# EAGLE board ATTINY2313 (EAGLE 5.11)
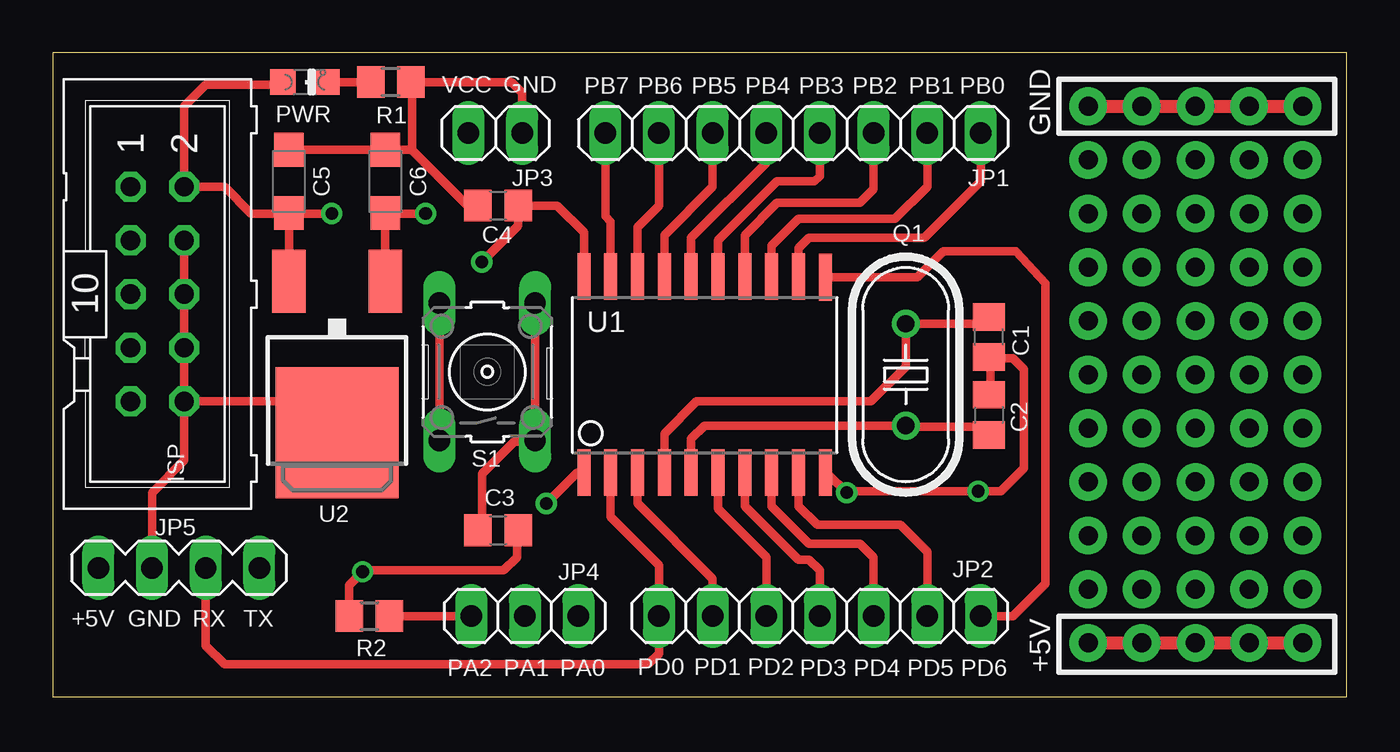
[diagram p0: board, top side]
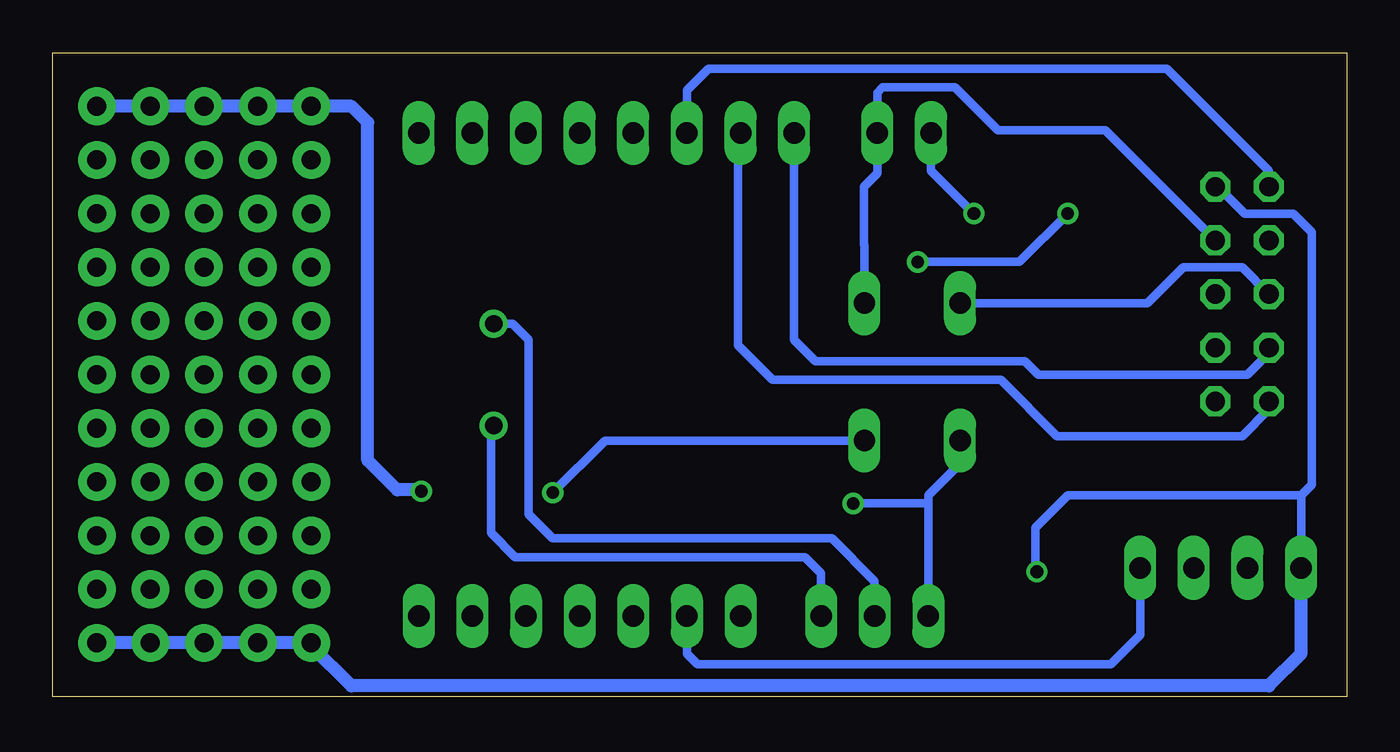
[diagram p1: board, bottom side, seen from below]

Size 61.27 x 30.47 mm. Coordinates in mm from the lower left corner, seen from the top.
Outline: 0,0 61.27,0 61.27,30.47 0,30.47 0,0
Copper layers (1*16): Top 0.035mm / dielectric 1.5mm / Bottom 0.035mm
Design rules "default": minimum track width 10mil, minimum drill 24mil, track to track 8mil, track to pad 8mil, pad to pad 8mil, via to via 8mil, smd to smd 8mil, copper to edge 40mil, drill to drill 8mil, minimum pad ring 10mil, minimum via ring 8mil, stop-mask expansion 4mil, vias tented up to drill 0mil, thermal gap 10mil

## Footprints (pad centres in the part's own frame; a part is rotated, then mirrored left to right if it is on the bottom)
C0805 = smd 1.3 x 1.5: 1 -0.95,0; 2 0.95,0
SMC_A = smd 1.6 x 1.4: + -1.5,0; - 1.5,0
ML10 = drill 0.914 octagon: 1 -5.08,-1.27; 2 -5.08,1.27; 3 -2.54,-1.27; 4 -2.54,1.27; 5 0,-1.27; 6 0,1.27; 7 2.54,-1.27; 8 2.54,1.27; 9 5.08,-1.27; 10 5.08,1.27
1X08 = drill 1.016 long: 1 -8.89,0; 2 -6.35,0; 3 -3.81,0; 4 -1.27,0; 5 1.27,0; 6 3.81,0; 7 6.35,0; 8 8.89,0
1X07 = drill 1.016 long: 1 -7.62,0; 2 -5.08,0; 3 -2.54,0; 4 0,0; 5 2.54,0; 6 5.08,0; 7 7.62,0
1X02 = drill 1.016 long: 1 -1.27,0; 2 1.27,0
1X03 = drill 1.016 long: 1 -2.54,0; 2 0,0; 3 2.54,0
MA04-1 = drill 1.016 long: 1 -3.81,0; 2 -1.27,0; 3 1.27,0; 4 3.81,0
CHIPLED_0805 = smd 1.2 x 1.2: A 0,-1.05; C 0,1.05
HC49U70 = drill 0.813 round: 1 -2.413,0; 2 2.413,0
R0805 = smd 1.3 x 1.5: 1 -0.95,0; 2 0.95,0
B3F-10XX = drill 1.016 long: 1 -3.251,2.261; 2 3.251,2.261; 3 -3.251,-2.261; 4 3.251,-2.261
SO20L$ = smd 0.61 x 2.21: 1 -5.715,-4.636; 2 -4.445,-4.636; 3 -3.175,-4.636; 4 -1.905,-4.636; 5 -0.635,-4.636; 6 0.635,-4.636; 7 1.905,-4.636; 8 3.175,-4.636; 9 4.445,-4.636; 10 5.715,-4.636; 11 5.715,4.61; 12 4.445,4.636; 13 3.175,4.636; 14 1.905,4.636; 15 0.635,4.636; 16 -0.635,4.636; 17 -1.905,4.636; 18 -3.175,4.636; 19 -4.445,4.636; 20 -5.715,4.636
DPACK = smd 1.6 x 3: 1 -2.28,-4.8; 3 2.28,-4.8 | smd 5.8 x 6.2: 4 0,2.38

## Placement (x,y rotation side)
C1  [C0805]  44.32,17.02 90 top
C2  [C0805]  44.32,13.33 270 top
C3  [C0805]  21.08,7.87 0 top
C4  [C0805]  21.08,23.24 0 top
C5  [SMC_A]  11.18,24.38 90 top
C6  [SMC_A]  15.75,24.38 90 top
ISP  [ML10]  4.95,19.05 270 top
JP1  [1X08]  35.05,26.67 0 top
JP2  [1X07]  36.32,3.81 180 top
JP3  [1X02]  20.95,26.67 0 top
JP4  [1X03]  22.35,3.81 180 top
JP5  AVTMOD09  [MA04-1]  5.97,6.1 0 top
PWR  [CHIPLED_0805]  11.94,29.08 270 top
Q1  [HC49U70]  40.39,15.24 90 top
R1  [R0805]  16,29.08 180 top
R2  [R0805]  14.99,3.81 0 top
S1  [B3F-10XX]  20.57,15.37 90 top
U1  TINY2313-*S*  [SO20L$]  30.86,15.24 0 top
U2  LP2950CDT-5.0  [DPACK]  13.46,14.86 180 top

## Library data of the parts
C1-C6 R1 R2 = rcl
ISP = con-ml
JP1-JP4 = pinhead
JP5 = con-lstb
PWR = led
Q1 = crystal
S1 = switch-omron
U1 = avr-6
U2 = v-reg

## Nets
GND: C1.1 C2.1 C3.1 C4.1 C5.- C6.- ISP.4 ISP.6 ISP.8 ISP.10 JP3.2 JP5.2 R1.1 S1.3 S1.4 U1.10 U2.4
N$6: PWR.C R1.2
PA0: C2.2 JP4.1 Q1.1 U1.5
PA1: C1.2 JP4.2 Q1.2 U1.4
PA2: ISP.5 JP4.3 R2.2 S1.1 S1.2 U1.1
PB0: JP1.8 U1.12
PB1: JP1.7 U1.13
PB2: JP1.6 U1.14
PB3: JP1.5 U1.15
PB4: JP1.4 U1.16
PB5: ISP.1 JP1.3 U1.17
PB6: ISP.9 JP1.2 U1.18
PB7: ISP.7 JP1.1 U1.19
PD0: JP2.7 JP5.3 U1.2
PD1: JP2.6 JP5.4 U1.3
PD2: JP2.5 U1.6
PD3: JP2.4 U1.7
PD4: JP2.3 U1.8
PD5: JP2.2 U1.9
PD6: JP2.1 U1.11
VCC: C3.2 C4.2 C5.+ ISP.2 JP5.1 PWR.A R2.1 U1.20 U2.3
VIN: C6.+ JP3.1 U2.1

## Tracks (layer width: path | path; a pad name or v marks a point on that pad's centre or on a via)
GND  (via drill 0.6, 0.9 pad 1.78)
  Top 0.406: 16.99,25.88 C6.- C5.- 16.99,25.88 | 17.02,25.91 17.02,29.02 R1.1 | C4.1 19.64,23.24 16.99,25.88 | ISP.4 ISP.6 ISP.8 ISP.10 | ISP.10 13.21,13.97 13.46,13.72 U2.4 | JP5.2 4.7,9.65 6.22,11.18 ISP.10 | S1.4 S1.3 22.78,12.06 21.84,12.06 20.32,10.54 20.32,8 20.19,7.87 C3.1 | 17.02,25.91 16.99,25.88 | 17.02,25.91 17.02,29.08 21.72,29.08 22.23,28.57 JP3.2 | v37.59,9.65 37.59,9.72 v43.81,9.72 | v43.81,9.72 44.9,9.72 45.97,10.79 45.97,15.49 45.47,16 44.39,16 | 44.39,16 C1.1 | 44.39,16 44.39,14.35 C2.1 | U1.10 36.64,10.6 v37.59,9.65 | v43.81,9.72 37.66,9.72 v37.59,9.65
  Top 0.61: v49.02,27.94 v59.18,27.94
  Bottom 0.406: ISP.4 11.43,26.8 16.51,26.8 18.54,28.83 21.97,28.83 22.23,28.57 JP3.2 22.23,24.76 22.86,24.13 22.86,21.39 22.84,21.36 S1.4 | S1.3 35.13,12.12 v37.59,9.65
  Bottom 0.61: 48.89,27.94 47.12,27.94 46.36,27.18 46.36,11.18 44.96,9.78 43.81,9.78 v43.81,9.72 | 48.89,27.94 v49.02,27.94 | 48.89,27.94 v59.18,27.94
N$2  (via drill 0.9 pad 1.78)
  other vias: 51.56,2.54
N$3  (via drill 0.9 pad 1.78)
  other vias: 54.1,2.54
N$4  (via drill 0.9 pad 1.78)
  other vias: 56.64,2.54
N$5  (via drill 0.9 pad 1.78)
  other vias: 59.18,2.54
N$6
  Top 0.406: PWR.C R1.2
N$12  (via drill 0.9 pad 1.78)
  other vias: 49.02,5.08
N$13  (via drill 0.9 pad 1.78)
  other vias: 51.56,5.08
N$14  (via drill 0.9 pad 1.78)
  other vias: 54.1,5.08
N$15  (via drill 0.9 pad 1.78)
  other vias: 56.64,5.08
N$16  (via drill 0.9 pad 1.78)
  other vias: 59.18,5.08
N$23  (via drill 0.9 pad 1.78)
  other vias: 49.02,7.62
N$24  (via drill 0.9 pad 1.78)
  other vias: 51.56,7.62
N$25  (via drill 0.9 pad 1.78)
  other vias: 54.1,7.62
N$26  (via drill 0.9 pad 1.78)
  other vias: 56.64,7.62
N$27  (via drill 0.9 pad 1.78)
  other vias: 59.18,7.62
N$34  (via drill 0.9 pad 1.78)
  other vias: 49.02,10.16
N$35  (via drill 0.9 pad 1.78)
  other vias: 51.56,10.16
N$36  (via drill 0.9 pad 1.78)
  other vias: 54.1,10.16
N$37  (via drill 0.9 pad 1.78)
  other vias: 56.64,10.16
N$38  (via drill 0.9 pad 1.78)
  other vias: 59.18,10.16
N$45  (via drill 0.9 pad 1.78)
  other vias: 49.02,12.7
N$46  (via drill 0.9 pad 1.78)
  other vias: 51.56,12.7
N$47  (via drill 0.9 pad 1.78)
  other vias: 54.1,12.7
N$48  (via drill 0.9 pad 1.78)
  other vias: 56.64,12.7
N$49  (via drill 0.9 pad 1.78)
  other vias: 59.18,12.7
N$56  (via drill 0.9 pad 1.78)
  other vias: 49.02,15.24
N$57  (via drill 0.9 pad 1.78)
  other vias: 51.56,15.24
N$58  (via drill 0.9 pad 1.78)
  other vias: 54.1,15.24
N$59  (via drill 0.9 pad 1.78)
  other vias: 56.64,15.24
N$60  (via drill 0.9 pad 1.78)
  other vias: 59.18,15.24
N$67  (via drill 0.9 pad 1.78)
  other vias: 49.02,17.78
N$68  (via drill 0.9 pad 1.78)
  other vias: 51.56,17.78
N$69  (via drill 0.9 pad 1.78)
  other vias: 54.1,17.78
N$70  (via drill 0.9 pad 1.78)
  other vias: 56.64,17.78
N$71  (via drill 0.9 pad 1.78)
  other vias: 59.18,17.78
N$78  (via drill 0.9 pad 1.78)
  other vias: 49.02,20.32
N$79  (via drill 0.9 pad 1.78)
  other vias: 51.56,20.32
N$80  (via drill 0.9 pad 1.78)
  other vias: 54.1,20.32
N$81  (via drill 0.9 pad 1.78)
  other vias: 56.64,20.32
N$82  (via drill 0.9 pad 1.78)
  other vias: 59.18,20.32
N$90  (via drill 0.9 pad 1.78)
  other vias: 49.02,22.86
N$91  (via drill 0.9 pad 1.78)
  other vias: 51.56,22.86
N$92  (via drill 0.9 pad 1.78)
  other vias: 54.1,22.86
N$93  (via drill 0.9 pad 1.78)
  other vias: 56.64,22.86
N$94  (via drill 0.9 pad 1.78)
  other vias: 59.18,22.86
N$95  (via drill 0.9 pad 1.78)
  other vias: 49.02,25.4
N$96  (via drill 0.9 pad 1.78)
  other vias: 51.56,25.4
N$97  (via drill 0.9 pad 1.78)
  other vias: 54.1,25.4
N$98  (via drill 0.9 pad 1.78)
  other vias: 56.64,25.4
N$99  (via drill 0.9 pad 1.78)
  other vias: 59.18,25.4
N$101  (via drill 0.9 pad 1.78)
  other vias: 51.56,27.94
N$102  (via drill 0.9 pad 1.78)
  other vias: 54.1,27.94
N$103  (via drill 0.9 pad 1.78)
  other vias: 56.64,27.94
PA0
  Top 0.406: U1.5 30.23,12.19 30.86,12.83 Q1.1 40.45,12.76 43.95,12.76 C2.2
  Bottom 0.406: JP4.1 24.89,5.84 25.65,6.6 39.37,6.6 40.51,7.75 40.51,12.7 Q1.1
PA1
  Top 0.406: U1.4 28.96,12.45 30.48,13.97 38.73,13.97 40.39,15.62 Q1.2 44.01,17.65 C1.2 44.13,17.65
  Bottom 0.406: JP4.2 22.35,5.46 24.38,7.49 37.59,7.49 38.73,8.64 38.73,16.89 39.5,17.65 Q1.2
PA2  (via drill 0.6)
  Top 0.406: R2.2 JP4.3 | S1.1 S1.2 | U1.1 24.83,10.6 v23.37,9.14
  Bottom 0.406: S1.1 18.31,11.02 19.81,9.52 19.81,9.14 | JP4.3 19.81,9.14 | S1.2 9.45,18.62 7.75,20.32 4.95,20.32 ISP.5 | 19.81,9.14 v23.37,9.14
PB0
  Top 0.406: U1.12 35.31,21.21 35.81,21.72 41.28,21.72 43.94,24.38 JP1.8
PB1
  Top 0.406: JP1.7 41.4,24.13 39.88,22.61 35.31,22.61 34.04,21.34 U1.13
PB2
  Top 0.406: JP1.6 38.86,24 38.23,23.37 34.29,23.37 32.77,21.84 U1.14
PB3
  Top 0.406: JP1.5 36.32,24.64 36.07,24.38 34.29,24.38 31.5,21.59 U1.15
PB4
  Top 0.406: JP1.4 33.78,25.27 30.23,21.72 U1.16
PB5
  Top 0.406: JP1.3 31.24,24.13 28.96,21.84 U1.17
  Bottom 0.406: ISP.1 3.68,24.89 8.51,29.72 30.23,29.72 31.24,28.7 JP1.3
PB6
  Top 0.406: JP1.2 28.7,23.24 27.69,22.22 U1.18
  Bottom 0.406: ISP.9 3.68,13.59 4.95,12.32 13.72,12.32 16.38,14.99 27.18,14.99 28.83,16.64 28.83,26.54 JP1.2
PB7
  Top 0.406: JP1.1 26.16,22.73 26.42,22.48 U1.19
  Bottom 0.406: ISP.7 3.68,16.26 4.7,15.24 14.61,15.24 15.24,15.87 25.15,15.87 26.16,16.89 JP1.1
PD0
  Top 0.406: U1.2 26.42,8.51 28.7,6.22 JP2.7 28.7,2.03 28.19,1.52 8.13,1.52 7.24,2.41 JP5.3
PD1
  Top 0.406: U1.3 27.69,9.14 31.24,5.59 JP2.6
  Bottom 0.406: JP5.4 9.78,2.92 11.18,1.52 30.73,1.52 31.24,2.03 JP2.6
PD2
  Top 0.406: U1.6 31.5,8.89 33.78,6.6 JP2.5
PD3
  Top 0.406: U1.7 32.77,9.02 35.31,6.48 35.81,6.48 36.32,5.97 JP2.4
PD4
  Top 0.406: U1.8 34.04,9.02 35.81,7.24 38.23,7.24 38.86,6.6 JP2.3
PD5
  Top 0.406: U1.9 35.31,9.02 36.19,8.13 40.13,8.13 41.4,6.86 JP2.2
PD6
  Top 0.406: U1.11 40.93,19.85 42.16,21.08 45.59,21.08 46.99,19.56 46.99,5.33 45.47,3.81 JP2.1
VCC  (via drill 0.6, 0.9 pad 1.78)
  Top 0.406: U2.3 C5.+ | U1.20 25.15,21.97 23.88,23.24 C4.2 22.03,22.29 v20.32,20.57 | R2.1 14.04,5.27 v14.67,5.91 14.73,5.97 21.34,5.97 21.97,6.6 21.97,7.81 C3.2 | C5.+ 11.15,22.86 9.4,22.86 8.13,24.13 ISP.2 6.22,27.94 7.24,28.96 10.67,28.96 10.79,29.08 PWR.A | v13.21,22.86 11.2,22.86 C5.+
  Top 0.61: v49.02,2.54 59.31,2.54
  Bottom 0.406: ISP.2 6.1,24.13 4.83,22.86 2.54,22.86 1.65,21.97 1.65,10.03 2.16,9.52 | v20.32,20.57 15.49,20.57 v13.21,22.86 | JP5.1 2.16,9.52 | 2.16,9.52 13.21,9.52 14.73,8 14.73,5.91 v14.67,5.91
  Bottom 0.61: JP5.1 2.16,2.03 3.68,0.51 47.12,0.51 49.02,2.41 v49.02,2.54 59.31,2.54
VIN  (via drill 0.6)
  Top 0.406: U2.1 C6.+ 15.77,22.86 v17.65,22.86
  Bottom 0.406: JP3.1 19.68,24.89 v17.65,22.86

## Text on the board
tNames: VCC | GND | PB7 | PB6 | PB5 | PB4 | PB3 | PB2 | PB1 | PB0 | GND | +5V | GND | RX | TX | PA2 | PA1 | PA0 | PD3 | PD4 | PD5 | PD6 | PD0 | PD1 | PD2 | +5V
